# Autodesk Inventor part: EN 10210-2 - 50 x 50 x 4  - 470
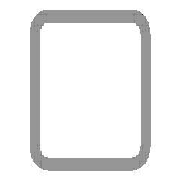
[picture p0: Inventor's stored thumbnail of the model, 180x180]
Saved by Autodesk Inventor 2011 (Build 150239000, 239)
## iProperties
IsCustomPart: 1
Created: 2020-12
Part Number: EN 10210-2 - 50 x 50 x 4  - 470
Material: Steel, Mild
Description: Tube 50*50*4
Document SubType Name: Modeling
Standard: DIN
Designer: PC
Standard Revision: 1997
Standards Organization: DIN
Language: en-US
Size Designation: 50 x 50 x 4
Categories: <MemberInstance><Categories><Category DisplayName="Structural Shapes" InternalName="089c4875-fa83-4c05-b084-43b9cc11f5ed" Mnemonic="GRDR"><CategoryParameter Dis
Stock Number: 50 x 50 x 4
Density: 7.86 g/cm^3
_CCFamilyMember: 15
_CCFamilyDisplayName: DIN EN 10219-2 (Square Hollow Section - Cold Formed) - Cold formed welded structural hollow sections of non-alloy and fine grain structural steel
_FrameMemberDoc: Frame Member File
_Version: 15.0.0
_GetPNFromCC: 1
G_L: 470.000 mm
G_W: 50.000 mm
G_H: 50.000 mm
+C9EA426D-D9F7-4518-AD77-3C4FC1C949F9+CUTDETAIL1: Miter 45.00 deg
+F4B11678-982F-45FD-8C75-207517ECF4D8+CUTDETAIL2: Miter 45.00 deg
Author: PC
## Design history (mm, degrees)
node "Start plane"
node "End plane"
sketch "Sketch"
  geometry: L1 (-25, -17)-(-25, 17); L2 (-17, 25)-(17, 25); L3 (25, 17)-(25, -17); L4 (17, -25)-(-17, -25); L5 (-17, 21)-(17, 21); L6 (21, 17)-(21, -17); L7 (17, -21)-(-17, -21); L8 (-21, -17)-(-21, 17); L9 (0, 37.32)-(0, -37.32) reference; L10 (-37.32, 0)-(37.32, 0) reference; A1 r 8 centre (-17, -17) between (-25, -17) and (-17, -25); A2 r 8 centre (-17, 17) between (-17, 25) and (-25, 17); A3 r 8 centre (17, 17) between (25, 17) and (17, 25); A4 r 8 centre (17, -17) between (17, -25) and (25, -17); A5 r 4 centre (-17, 17) between (-17, 21) and (-21, 17); A6 r 4 centre (17, 17) between (21, 17) and (17, 21); A7 r 4 centre (17, -17) between (17, -21) and (21, -17); A8 r 4 centre (-17, -17) between (-21, -17) and (-17, -21)
  constraints: 16 end point, 16 point on circle, 8 centre point, 8 tangent, 4 parallel, 3 equal radius, 2 perpendicular, 7 other
  dimensions: "d7" = 8 radius of A1 (= G_IR); "d10" = 50 distance between parallel lines of L2 L4 (= G_H); "d11" = 50 distance between parallel lines of L1 L3 (= G_W); "d12" = 4 distance between parallel lines of L3 L6 (= G_T); "d15" = 25 distance between parallel lines of L2 L10 (= 0.5 x d10); "d16" = 25 distance between parallel lines of L9 L3 (= 0.5 x d11)
extrude "Body" new body sketch "Sketch" stored distance "d3" = 470 (= G_L); taper "d4" = 0 deg
node "Driven Length"
  sketch "Sketch3"
    geometry: L1 (0, 0)-(10, 0) reference
    constraints: 2 end point, 1 horizontal
  workplane "Work Plane3"
  sketch "Sketch4"
    geometry: L1 (-2, 0)-(12, 0) reference; L2 (-2, 470)-(12, 470) reference
    dimensions: "d18" = 470 distance between parallel lines of L1 L2 (derived)
workplane "Work Plane4"
split "Split1"
workplane "Work Plane5"
split "Split2"
body "Solid1"
other parameters: "G_W" = 50 [user parameter; used in 1 equation term], "G_H" = 50 [user parameter; used in 1 equation term], "G_T" = 4 [user parameter; used in 1 equation term], "G_IR" = 8 [user parameter; used in 1 equation term], "G_L" = 470 (= d18) [user parameter; used in 1 equation term], "G_OFFSET_START" = 0 [user parameter; used in 1 equation term], "G_OFFSET_END" = 0 [user parameter; used in 1 equation term], "d13" = 0 (computed from G_OFFSET_START), "d17" = 90 deg
